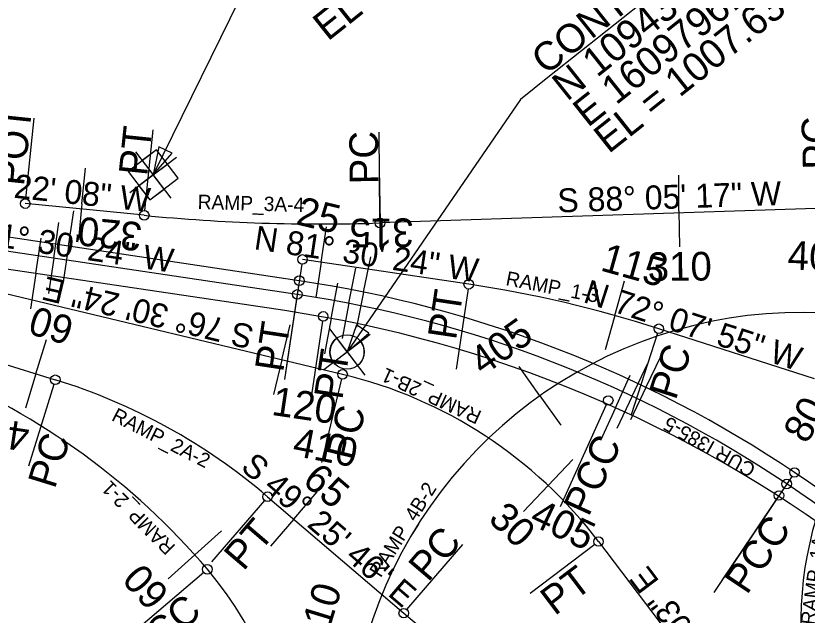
# Model space of a CAD drawing. Extents: x 1603447 to 1622636, y 1083818 to 1103958.
# Drawn here: x 1609242 to 1610566, y 1093865 to 1094869 of the extents above; entities that cross this region are included whole.
import ezdxf

# ---------------------------------------------------------------- set-up
doc = ezdxf.new("R2010")
doc.units = 0
for name, color, linetype in [('Level 1', 7, 'Continuous'), ('RD_HC_Points', 7, 'Continuous'), ('RD_HC_SUR_Bearing_TX400', 7, 'Continuous'), ('RD_HC_SUR_CL400', 7, 'Continuous'), ('RD_HC_SUR_PC_PT_400', 7, 'Continuous'), ('RD_HC_SUR_Tic400', 7, 'Continuous'), ('RD_HC_SUR_TX_Sta400', 7, 'Continuous'), ('RD_SHT_Misc1', 7, 'Continuous'), ('RD_TX_Misc1', 7, 'Continuous')]:
    doc.layers.add(name, color=color, linetype=linetype)

msp = doc.modelspace()

# ---------------------------------------------------------------- linework, layer by layer
at = {"layer": 'Level 1'}
msp.add_line((1609556.2, 1093936.7), (1609413.5, 1093815.2), dxfattribs=at)
msp.add_circle((1609562.3, 1093941.9), 8, dxfattribs=at)
at = {"layer": 'RD_HC_Points'}
msp.add_line((1610537.3, 1095087.9), (1610131.9, 1094765.4), dxfattribs=at)
for points in [[(1609661.8, 1094953.8), (1609632.3, 1094930.3), (1609471.6, 1094602.5)], [(1610131.9, 1094765.4), (1610086.2, 1094729), (1609796.2, 1094306)]]:
    msp.add_lwpolyline(points, dxfattribs=at)
for points in [[(1609480.9, 1094649.6), (1609471.6, 1094602.5), (1609503.2, 1094638.7)], [(1609812.2, 1094351.2), (1609796.2, 1094306), (1609832.7, 1094337.2)]]:
    msp.add_lwpolyline(points, close=True, dxfattribs=at)
at = {"layer": 'RD_HC_SUR_CL400'}
for p, q in [((1609456.7, 1094534.8), (1609257.5, 1094554.4)), ((1610967.7, 1094559.3), (1609851.2, 1094522)), ((1609716.2, 1094425.3), (1608991.5, 1094533.5)), ((1609712.8, 1094402.3), (1608988, 1094510.5)), ((1609691.8, 1094375.1), (1608983.5, 1094480.9)), ((1609999.8, 1094419.3), (1609721.5, 1094460.9)), ((1609039.4, 1094448.2), (1609788.6, 1094268.5)), ((1608856.7, 1094398.7), (1609307.8, 1094259.4)), ((1610578.6, 1094260.8), (1610318, 1094344.8)), ((1609663.1, 1094063.5), (1609891, 1093868.4)), ((1610217, 1093988.4), (1610529.9, 1093575.5))]:
    msp.add_line(p, q, dxfattribs=at)
for centre, radius, start, end in [((1609751.1, 1097520.3), 3000, 264.3689, 271.912), ((1609417.4, 1092424.2), 2023.2, 56.1301, 81.5065), ((1609704.4, 1092441.3), 2000, 72.1319, 81.5065), ((1611155.6, 1093853.7), 600, 109.8521, 236.724), ((1609417.4, 1092424.2), 2000, 56.1301, 81.5065), ((1609381.3, 1092295.5), 2102.7, 53.0731, 81.5065), ((1610558.2, 1093612.3), 760, 18.4471, 165.9491), ((1608648.5, 1093164.1), 1200, 40.4045, 67.546), ((1609012.7, 1093303.9), 1000, 49.4294, 72.8371), ((1609611.3, 1093529.4), 760, 37.1508, 76.5065), ((1608910.9, 1091669.6), 2932.1, 37.9336, 56.1301), ((1608910.9, 1091669.6), 2908.8, 39.6334, 56.1301), ((1609105.4, 1093553), 600, 323.4116, 40.4045), ((1610606.4, 1094704), 1100, 229.4294, 303.6278)]:
    msp.add_arc(centre, radius, start, end, dxfattribs=at)
at = {"layer": 'RD_HC_SUR_PC_PT_400'}
for p, q in [((1609258.3, 1094562.4), (1609272.5, 1094697.5)), ((1609457.6, 1094542.8), (1609471.8, 1094677.8)), ((1609851.1, 1094530), (1609849.8, 1094673.8)), ((1609720.3, 1094453), (1609693.3, 1094271.6)), ((1609715, 1094417.4), (1609695, 1094283)), ((1609998.6, 1094411.4), (1609978.5, 1094277.1)), ((1609711.6, 1094394.4), (1609691.5, 1094260)), ((1609755, 1094357.6), (1609735, 1094223.2)), ((1610315.6, 1094337.2), (1610271.5, 1094200.4)), ((1609786.7, 1094260.7), (1609753.2, 1094120.9)), ((1609305.4, 1094251.7), (1609263, 1094114.4)), ((1610230, 1094217.4), (1610152.6, 1094046.7)), ((1610540.5, 1094097.5), (1610436, 1093941.8)), ((1610527.5, 1094078.2), (1610423.1, 1093922.5)), ((1609657.9, 1094057.4), (1609569.5, 1093954.3)), ((1610514.6, 1094058.9), (1610410.1, 1093903.2)), ((1609896.2, 1093874.5), (1609989.7, 1093983.7)), ((1610210.6, 1093983.6), (1610102.4, 1093901.6))]:
    msp.add_line(p, q, dxfattribs=at)
for centre in [(1609257.5, 1094554.4), (1609456.7, 1094534.8), (1609851.2, 1094522), (1609721.5, 1094460.9), (1609716.2, 1094425.3), (1609999.8, 1094419.3), (1609712.8, 1094402.3), (1609756.2, 1094365.5), (1610318, 1094344.8), (1609788.6, 1094268.5), (1609307.8, 1094259.4), (1610233.3, 1094224.7), (1610545, 1094104.1), (1610532, 1094084.8), (1609663.1, 1094063.5), (1610519, 1094065.5), (1610217, 1093988.4), (1609891, 1093868.4)]:
    msp.add_circle(centre, 8, dxfattribs=at)
at = {"layer": 'RD_HC_SUR_Tic400'}
for p, q in [((1609352.3, 1094553.9), (1609358.1, 1094613.7)), ((1610351.7, 1094542.1), (1610351.2, 1094602.1)), ((1609851.7, 1094537.4), (1609851.2, 1094597.4)), ((1609352.3, 1094553.9), (1609346.5, 1094494.2)), ((1609329.8, 1094483), (1609338.7, 1094542.3)), ((1609452, 1094545.6), (1609452, 1094545.6)), ((1609452, 1094545.6), (1609452, 1094545.6)), ((1609551.8, 1094539.9), (1609551.8, 1094539.9)), ((1609551.8, 1094539.9), (1609551.8, 1094539.9)), ((1609651.8, 1094536.9), (1609651.8, 1094536.9)), ((1609651.8, 1094536.9), (1609651.8, 1094536.9)), ((1609751.7, 1094536.4), (1609751.7, 1094536.4)), ((1609751.7, 1094536.4), (1609751.7, 1094536.4)), ((1609851.7, 1094537.4), (1609852.3, 1094477.4)), ((1610351.7, 1094542.1), (1610352.3, 1094482.1)), ((1609305.1, 1094463.2), (1609313.9, 1094522.5)), ((1609752.7, 1094456.2), (1609761.5, 1094515.6)), ((1609275.1, 1094437.3), (1609284, 1094496.6)), ((1609329.8, 1094483), (1609321, 1094423.6)), ((1609428.7, 1094468.2), (1609428.7, 1094468.2)), ((1609305.1, 1094463.2), (1609296.2, 1094403.8)), ((1609752.7, 1094456.2), (1609743.8, 1094396.9)), ((1609823.8, 1094406.2), (1609835.9, 1094465)), ((1609404, 1094448.4), (1609404, 1094448.4)), ((1609527.6, 1094453.4), (1609527.6, 1094453.4)), ((1609799.3, 1094387.4), (1609810.7, 1094446.3)), ((1609851.6, 1094441.5), (1609851.6, 1094441.5)), ((1609275.1, 1094437.3), (1609266.3, 1094378)), ((1609502.9, 1094433.6), (1609502.9, 1094433.6)), ((1609626.5, 1094438.7), (1609626.5, 1094438.7)), ((1609374, 1094422.5), (1609374, 1094422.5)), ((1609601.8, 1094418.9), (1609601.8, 1094418.9)), ((1609725.4, 1094423.9), (1609725.4, 1094423.9)), ((1609769.4, 1094362), (1609780.5, 1094421)), ((1609950.5, 1094426.7), (1609950.5, 1094426.7)), ((1610244.2, 1094367), (1610260.4, 1094424.8)), ((1609473, 1094407.8), (1609473, 1094407.8)), ((1609700.7, 1094404.1), (1609700.7, 1094404.1)), ((1609823.8, 1094406.2), (1609811.8, 1094347.4)), ((1610049.3, 1094411.3), (1610049.3, 1094411.3)), ((1609571.9, 1094393), (1609571.9, 1094393)), ((1610147.3, 1094391.6), (1610147.3, 1094391.6)), ((1609298.1, 1094386.2), (1609298.1, 1094386.2)), ((1609670.8, 1094378.2), (1609670.8, 1094378.2)), ((1609799.3, 1094387.4), (1609787.8, 1094328.5)), ((1609921.3, 1094383.7), (1609921.3, 1094383.7)), ((1609395.4, 1094362.8), (1609395.4, 1094362.8)), ((1609769.4, 1094362), (1609758.3, 1094303)), ((1609896.9, 1094365.9), (1609896.9, 1094365.9)), ((1610244.2, 1094367), (1610228, 1094309.3)), ((1610490, 1094369.2), (1610490, 1094369.2)), ((1609687.1, 1094292.8), (1609701.1, 1094351.2)), ((1610017.5, 1094356.4), (1610017.5, 1094356.4)), ((1610391.3, 1094353.7), (1610391.3, 1094353.7)), ((1609492.6, 1094339.5), (1609492.6, 1094339.5)), ((1609867.2, 1094341.2), (1609867.2, 1094341.2)), ((1609993.4, 1094339.5), (1609993.4, 1094339.5)), ((1610339.8, 1094337.8), (1610339.8, 1094337.8)), ((1609275.5, 1094269.4), (1609293.2, 1094326.7)), ((1610112.2, 1094324.4), (1610112.2, 1094324.4)), ((1610295.5, 1094325.4), (1610295.5, 1094325.4)), ((1610295.5, 1094325.4), (1610295.5, 1094325.4)), ((1609589.8, 1094316.2), (1609589.8, 1094316.2)), ((1609963.9, 1094315.8), (1609963.9, 1094315.8)), ((1610088.4, 1094308.3), (1610088.4, 1094308.3)), ((1610296.3, 1094246.6), (1610322.4, 1094300.6)), ((1610435, 1094307.1), (1610435, 1094307.1)), ((1609687.1, 1094292.8), (1609673.1, 1094234.5)), ((1610059.3, 1094285.8), (1610059.3, 1094285.8)), ((1610204.2, 1094284.8), (1610204.2, 1094284.8)), ((1610204.2, 1094284.8), (1610204.2, 1094284.8)), ((1610205.2, 1094287.8), (1610205.2, 1094287.8)), ((1610273.1, 1094231.9), (1610298.8, 1094286.1)), ((1609275.5, 1094269.4), (1609257.8, 1094212)), ((1609784.3, 1094269.5), (1609784.3, 1094269.5)), ((1610119, 1094232.5), (1610084.3, 1094281.5)), ((1610181.7, 1094272.4), (1610181.7, 1094272.4)), ((1610530.2, 1094276.4), (1610530.2, 1094276.4)), ((1610245.3, 1094212.4), (1610269.9, 1094267.1)), ((1610153.2, 1094251.3), (1610153.2, 1094251.3)), ((1610296.3, 1094246.6), (1610270.3, 1094192.5)), ((1609370.3, 1094237.8), (1609370.3, 1094237.8)), ((1609879.9, 1094240.4), (1609879.9, 1094240.4)), ((1610119, 1094232.5), (1610153.7, 1094183.5)), ((1610273.1, 1094231.9), (1610247.4, 1094177.7)), ((1610245.3, 1094212.4), (1610220.6, 1094157.7)), ((1609461.8, 1094197.4), (1609461.8, 1094197.4)), ((1609970.9, 1094199), (1609970.9, 1094199)), ((1610385.3, 1094200.9), (1610385.3, 1094200.9)), ((1610362.4, 1094186.9), (1610362.4, 1094186.9)), ((1610041.4, 1094169.5), (1610041.4, 1094169.5)), ((1610335.4, 1094169.2), (1610335.4, 1094169.2)), ((1609315.1, 1094161.9), (1609315.1, 1094161.9)), ((1610471.9, 1094150.9), (1610471.9, 1094150.9)), ((1609548.7, 1094148.1), (1609548.7, 1094148.1)), ((1610055.6, 1094146), (1610055.6, 1094146)), ((1610449.3, 1094137.4), (1610449.3, 1094137.4)), ((1610132.6, 1094082.4), (1610173.8, 1094126)), ((1610423.4, 1094121.7), (1610423.4, 1094121.7)), ((1609395.8, 1094103), (1609395.8, 1094103)), ((1609972.8, 1094096.9), (1609972.8, 1094096.9)), ((1610555.9, 1094096.7), (1610555.9, 1094096.7)), ((1609630.3, 1094090.4), (1609630.3, 1094090.4)), ((1610533.6, 1094083.7), (1610533.6, 1094083.7)), ((1609706.9, 1094026), (1609745.9, 1094071.6)), ((1610132.6, 1094082.4), (1610091.5, 1094038.7)), ((1610509.1, 1094070.1), (1610509.1, 1094070.1)), ((1609471.4, 1094037.5), (1609471.4, 1094037.5)), ((1609706.9, 1094026), (1609667.8, 1093980.5)), ((1609541.2, 1093966), (1609585.9, 1094006.1)), ((1609914.2, 1094015.9), (1609914.2, 1094015.9)), ((1610200.7, 1094009.2), (1610200.7, 1094009.2)), ((1609541.2, 1093966), (1609496.6, 1093925.9)), ((1609782.8, 1093961), (1609782.8, 1093961)), ((1610565.4, 1093961.8), (1610565.4, 1093961.8)), ((1609866.9, 1093927.9), (1609866.9, 1093927.9)), ((1610261.4, 1093929.8), (1610261.4, 1093929.8)), ((1609603.3, 1093887.8), (1609603.3, 1093887.8))]:
    msp.add_line(p, q, dxfattribs=at)
at = {"layer": 'RD_SHT_Misc1'}
for p, q in [((1609442.1, 1094641.3), (1609501.1, 1094563.7)), ((1609432.8, 1094573), (1609510.4, 1094632)), ((1609453.4, 1094626.4), (1609471.6, 1094602.5)), ((1609471.6, 1094602.5), (1609495.5, 1094620.7)), ((1609471.6, 1094602.5), (1609447.7, 1094584.4)), ((1609489.8, 1094578.7), (1609471.6, 1094602.5)), ((1609757.4, 1094276.5), (1609835, 1094335.5)), ((1609766.7, 1094344.8), (1609825.7, 1094267.2)), ((1609796.2, 1094306), (1609778.8, 1094328.9)), ((1609819.1, 1094323.4), (1609796.2, 1094306)), ((1609773.3, 1094288.6), (1609796.2, 1094306)), ((1609796.2, 1094306), (1609813.6, 1094283.1))]:
    msp.add_line(p, q, dxfattribs=at)
msp.add_lwpolyline([(1609465.9, 1094560.5), (1609513.6, 1094596.8), (1609477.3, 1094644.6), (1609429.6, 1094608.3)], close=True, dxfattribs=at)
for points in [[(1609495.5, 1094620.7), (1609477.3, 1094644.6), (1609453.4, 1094626.4)], [(1609447.7, 1094584.4), (1609465.9, 1094560.5)], [(1609465.9, 1094560.5), (1609489.8, 1094578.7)]]:
    msp.add_lwpolyline(points, dxfattribs=at)
msp.add_circle((1609796.2, 1094306), 28.8, dxfattribs=at)
for start, end in [(127.2464, 217.2464), (307.2464, 37.2464)]:
    msp.add_arc((1609796.2, 1094306), 28.8, start, end, dxfattribs=at)

# ---------------------------------------------------------------- texts
at = {"layer": 'Level 1'}
for s, rotation, p in [('315', 180.537, (1609907.4, 1094529.8)), ('115', 344.3409, (1610218.4, 1094442.8)), ('405', 35.3019, (1610023.7, 1094264.9)), ('415', 171.5065, (1609266.9, 1094186.1)), ('65', 319.4294, (1609719.3, 1094087.2)), ('405', 334.6678, (1610099.3, 1094018.1)), ('PCC', 40.4045, (1609452.1, 1093779.4))]:
    msp.add_text(s, height=48, rotation=rotation, dxfattribs=at).set_placement(p)
at = {"layer": 'RD_HC_Points'}
for s, p in [('CONTROL L2-230', (1610129.4, 1094768.5)), ('EL = 1015.14', (1609763.9, 1094825.4)), ('N 1094305.9806', (1610164.3, 1094724.7)), ('E 1609796.1906', (1610199.1, 1094680.9)), ('EL = 1007.63', (1610234, 1094637))]:
    msp.add_text(s, height=48, rotation=38.4995, dxfattribs=at).set_placement(p)
at = {"layer": 'RD_HC_SUR_Bearing_TX400'}
for s, rotation, p in [('N 84%%d 22\' 08" W', 353.9996, (1609088.9, 1094579.9)), ('S 88%%d 05\' 17" W', 1.912, (1610148.9, 1094539.5)), ('N 81%%d 30\' 24" W', 351.5065, (1609128.8, 1094494.5)), ('N 81%%d 30\' 24" W', 351.5065, (1609639.1, 1094478.2)), ('S 76%%d 30\' 24" E', 166.5065, (1609642.5, 1094349.1)), ('N 72%%d 07\' 55" W', 342.1319, (1610189.6, 1094389.9)), ('S 49%%d 25\' 46" E', 319.4294, (1609616.3, 1094110.1)), ('S 37%%d 09\' 03" E', 127.1508, (1610515.9, 1093663.2))]:
    msp.add_text(s, height=40, rotation=rotation, dxfattribs=at).set_placement(p)
at = {"layer": 'RD_HC_SUR_PC_PT_400'}
for s, rotation, p in [('POT', 83.9996, (1609255.2, 1094582.9)), ('PC', 91.912, (1610607.2, 1094612.3)), ('PT', 83.9996, (1609461.5, 1094599.7)), ('PC', 90.537, (1609848.6, 1094587)), ('PT', 81.5065, (1609978.4, 1094324.9)), ('PT', 81.5065, (1609689.1, 1094271)), ('PT', 81.5065, (1609788.1, 1094224.8)), ('PC', 72.1319, (1610346.2, 1094223.8)), ('PC', 76.5065, (1609807, 1094122.6)), ('PC', 72.8371, (1609307, 1094075.2)), ('PCC', 65.621, (1610200.4, 1094028.6)), ('PT', 49.4294, (1609622.7, 1093937.7)), ('PCC', 56.1301, (1610465.3, 1093897.8)), ('PC', 49.4294, (1609931.7, 1093919.1)), ('PT', 37.1508, (1610143.7, 1093863.1))]:
    msp.add_text(s, height=48, rotation=rotation, dxfattribs=at).set_placement(p)
at = {"layer": 'RD_HC_SUR_TX_Sta400'}
for s, rotation, p in [('25', 346.5065, (1609708.7, 1094520.1)), ('320', 174.4755, (1609454.7, 1094522.3)), ('400', 357.6073, (1610532.9, 1094444.4)), ('310', 0.537, (1610299.7, 1094424.7)), ('60', 162.8371, (1609342.2, 1094362.4)), ('120', 351.5065, (1609668.3, 1094200.7)), ('80', 60.5147, (1610565.7, 1094150.2)), ('410', 348.9917, (1609703.2, 1094132.8)), ('30', 316.6821, (1610030.6, 1094023.9)), ('60', 131.9345, (1609500.9, 1093902)), ('410', 72.9965, (1609756.6, 1093807.1))]:
    msp.add_text(s, height=48, rotation=rotation, dxfattribs=at).set_placement(p)
at = {"layer": 'RD_TX_Misc1'}
for s, rotation, p in [('RAMP_3A-4', 358.2746, (1609545.8, 1094545.6)), ('RAMP_1-3', 349.0495, (1610060.5, 1094418)), ('RAMP_2B-1', 155.3735, (1610023.2, 1094205.9)), ('RAMP_2A-2', 332.9043, (1609400.3, 1094192)), ('CUR I385-5', 150.5984, (1610482.2, 1094115.5)), ('RAMP_2-1', 134.6875, (1609510.5, 1093980.7)), ('RAMP_4B-2', 57.9675, (1609852.4, 1093926.7)), ('RAMP_1A-4', 82.2275, (1610578.7, 1093847.6))]:
    msp.add_text(s, height=24, rotation=rotation, dxfattribs=at).set_placement(p)

doc.saveas('drawing.dxf')
